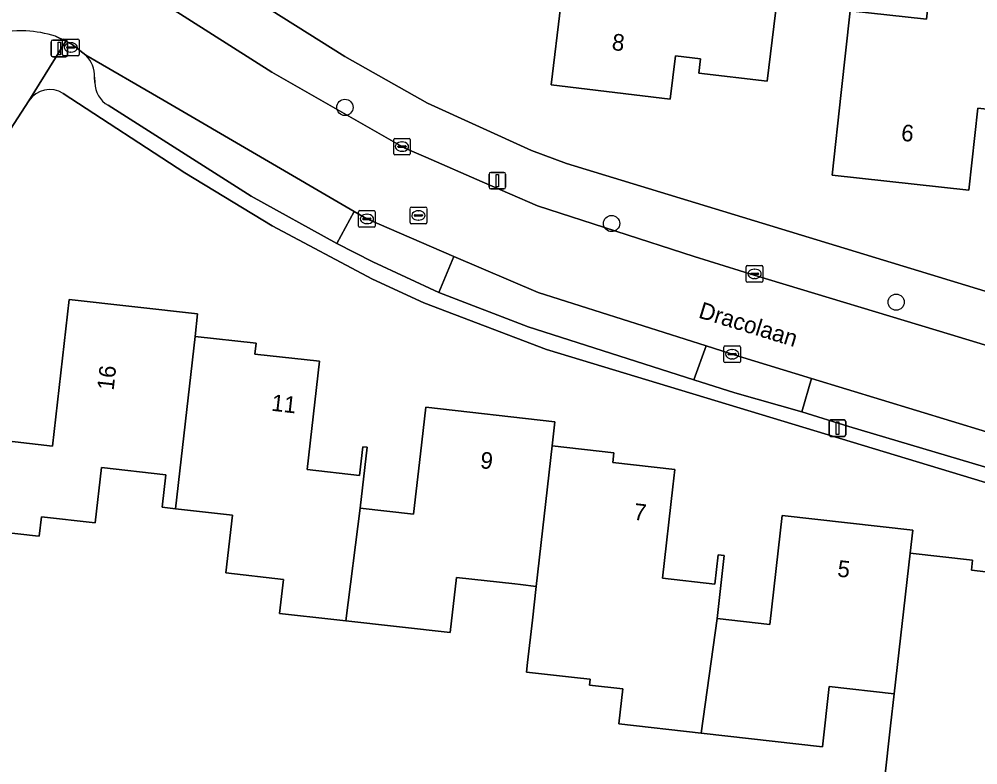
# Model space of a CAD drawing. Extents: x 162396 to 163643, y 386452 to 387406.
# Drawn here: x 162776.3 to 162834, y 386703.6 to 386748.5 of the extents above; entities that cross this region are included whole.
import ezdxf

# ---------------------------------------------------------------- set-up
doc = ezdxf.new("R2010")
doc.units = 0
for name, color, linetype in [('IMGEO_Boom', 7, 'Continuous'), ('IMGEO_Erf', 7, 'Continuous'), ('IMGEO_Kolk', 7, 'Continuous'), ('IMGEO_Lichtmast', 7, 'Continuous'), ('IMGEO_Openbare_ruimte_label', 7, 'Continuous'), ('IMGEO_Pand', 7, 'Continuous'), ('IMGEO_Pand_nummerreeks', 7, 'Continuous'), ('IMGEO_Parkeervlak_open', 7, 'Continuous'), ('IMGEO_Rijbaan_lokaal_open', 7, 'Continuous'), ('IMGEO_Rioolput', 7, 'Continuous'), ('IMGEO_Voetpad_open', 7, 'Continuous')]:
    doc.layers.add(name, color=color, linetype=linetype)

msp = doc.modelspace()

# ---------------------------------------------------------------- linework, layer by layer
at = {"layer": 'IMGEO_Boom'}
for centre in [(162795.943, 386743.185), (162811.991, 386736.195), (162829.12, 386731.463)]:
    msp.add_circle(centre, 0.489, dxfattribs=at)
at = {"layer": 'IMGEO_Erf'}
for points in [[(162821.361, 386744.761), (162817.252, 386745.249), (162817.354, 386746.114), (162815.837, 386746.294), (162815.528, 386743.687), (162808.365, 386744.537), (162808.938, 386749.367), (162810.208, 386749.217), (162810.301, 386750), (162810.679, 386753.193), (162814.991, 386752.681), (162815.198, 386754.42), (162822.406, 386753.564), (162821.983, 386750), (162821.951, 386749.727)], [(162838.302, 386750.511), (162838.246, 386750), (162837.996, 386747.728), (162837.45, 386742.757), (162834.043, 386743.131), (162833.501, 386738.198), (162825.263, 386739.102), (162825.809, 386744.073), (162826.351, 386749.005), (162830.938, 386748.501), (162831.102, 386750), (162831.243, 386751.286), (162831.558, 386754.158), (162838.618, 386753.383)]]:
    msp.add_lwpolyline(points, close=True, dxfattribs=at)
for points in [[(162784.935, 386753.194), (162789.995, 386750), (162795.943, 386746.246), (162800.923, 386743.431), (162807.171, 386740.595), (162809.276, 386739.81), (162887.231, 386716.025)], [(162879.195, 386707.065), (162808.069, 386728.604), (162800.69, 386731.432), (162797.61, 386732.851), (162791.569, 386736.058), (162786.318, 386739.251), (162778.985, 386744.019)], [(162776.93, 386743.582), (162768.744, 386730.951), (162762.934, 386721.672), (162757.742, 386711.279), (162754.454, 386701.785), (162744.409, 386671.894), (162782.247, 386667.715), (162783.774, 386663.035), (162787.296, 386663.004), (162855.09, 386662.415)], [(162772.963, 386723.411), (162778.345, 386722.803), (162779.342, 386731.632), (162787.082, 386730.758), (162786.929, 386729.402), (162790.603, 386728.987), (162790.531, 386728.342), (162794.407, 386727.904), (162793.671, 386721.384), (162796.818, 386721.029), (162797.014, 386722.763), (162797.275, 386722.734), (162796.86, 386719.058), (162800.076, 386718.694), (162800.487, 386722.334), (162800.805, 386725.144), (162808.582, 386724.266), (162808.418, 386722.814), (162812.126, 386722.395), (162812.06, 386721.812), (162815.793, 386721.39), (162815.676, 386720.357), (162815.054, 386714.85), (162818.204, 386714.494), (162818.402, 386716.251), (162818.772, 386716.209), (162818.344, 386712.421), (162821.52, 386712.063), (162822.261, 386718.623), (162830.115, 386717.736), (162829.959, 386716.349), (162833.716, 386715.925), (162833.648, 386715.325), (162837.431, 386714.898)], [(162828.414, 386702.69), (162828.787, 386705.967), (162829.003, 386707.886), (162825.088, 386708.328), (162824.678, 386704.697), (162817.389, 386705.52), (162812.438, 386706.079), (162812.676, 386708.181), (162810.666, 386708.408), (162810.706, 386708.763), (162810.123, 386708.829), (162806.875, 386709.197), (162806.94, 386709.77), (162807.229, 386712.318), (162807.46, 386714.357), (162806.521, 386714.463), (162806.173, 386714.502), (162802.655, 386714.9), (162802.279, 386711.571), (162795.993, 386712.28), (162795.279, 386712.361), (162792.011, 386712.729), (162792.242, 386714.78), (162788.784, 386715.171), (162789.176, 386718.646), (162785.758, 386719.032), (162784.943, 386719.124), (162785.164, 386721.078), (162781.289, 386721.516), (162780.911, 386718.176), (162777.685, 386718.541), (162777.553, 386717.373), (162777.316, 386717.4), (162772.347, 386717.961)]]:
    msp.add_lwpolyline(points, dxfattribs=at)
msp.add_arc((162778.176, 386742.773), 1.486, 57.01486, 146.99561, dxfattribs=at)
at = {"layer": 'IMGEO_Kolk'}
for p, q in [((162778.947, 386746.37), (162778.947, 386747.222)), ((162779.022, 386747.296), (162779.874, 386747.296)), ((162779.435, 386747.076), (162779.46, 386747.076)), ((162779.948, 386747.222), (162779.948, 386746.37)), ((162779.206, 386746.79), (162779.206, 386746.802)), ((162779.644, 386746.753), (162779.246, 386746.753)), ((162779.249, 386746.839), (162779.647, 386746.839)), ((162779.458, 386746.516), (162779.433, 386746.516)), ((162779.69, 386746.802), (162779.69, 386746.79)), ((162779.874, 386746.296), (162779.022, 386746.296)), ((162798.953, 386741.323), (162799.805, 386741.323)), ((162798.878, 386740.397), (162798.878, 386741.249)), ((162799.137, 386740.817), (162799.137, 386740.829)), ((162799.575, 386740.78), (162799.177, 386740.78)), ((162799.18, 386740.866), (162799.578, 386740.866)), ((162799.366, 386741.103), (162799.391, 386741.103)), ((162799.621, 386740.829), (162799.621, 386740.817)), ((162799.879, 386741.249), (162799.879, 386740.397)), ((162799.805, 386740.323), (162798.953, 386740.323)), ((162799.389, 386740.543), (162799.364, 386740.543)), ((162796.768, 386736.044), (162796.768, 386736.896)), ((162796.843, 386736.97), (162797.695, 386736.97)), ((162797.256, 386736.75), (162797.281, 386736.75)), ((162797.769, 386736.896), (162797.769, 386736.044)), ((162797.027, 386736.464), (162797.027, 386736.476)), ((162797.465, 386736.427), (162797.067, 386736.427)), ((162797.07, 386736.513), (162797.468, 386736.513)), ((162797.279, 386736.19), (162797.254, 386736.19)), ((162797.511, 386736.476), (162797.511, 386736.464)), ((162797.695, 386735.97), (162796.843, 386735.97)), ((162820.097, 386732.736), (162820.097, 386733.588)), ((162820.172, 386733.662), (162821.024, 386733.662)), ((162820.585, 386733.442), (162820.61, 386733.442)), ((162821.098, 386733.588), (162821.098, 386732.736)), ((162821.024, 386732.662), (162820.172, 386732.662)), ((162820.356, 386733.156), (162820.356, 386733.168)), ((162820.794, 386733.119), (162820.396, 386733.119)), ((162820.399, 386733.205), (162820.797, 386733.205)), ((162820.608, 386732.882), (162820.583, 386732.882)), ((162820.84, 386733.168), (162820.84, 386733.156)), ((162818.751, 386727.9), (162818.751, 386728.752)), ((162818.826, 386728.826), (162819.678, 386728.826)), ((162819.752, 386728.752), (162819.752, 386727.9)), ((162819.01, 386728.32), (162819.01, 386728.332)), ((162819.448, 386728.283), (162819.05, 386728.283)), ((162819.053, 386728.369), (162819.451, 386728.369)), ((162819.262, 386728.046), (162819.237, 386728.046)), ((162819.239, 386728.606), (162819.264, 386728.606)), ((162819.494, 386728.332), (162819.494, 386728.32)), ((162819.678, 386727.826), (162818.826, 386727.826))]:
    msp.add_line(p, q, dxfattribs=at)
for points in [[(162778.947, 386746.37), (162778.947, 386747.222)], [(162779.022, 386747.296), (162779.874, 386747.296)], [(162779.948, 386747.222), (162779.948, 386746.37)], [(162779.874, 386746.296), (162779.022, 386746.296)], [(162798.953, 386741.323), (162799.805, 386741.323)], [(162798.878, 386740.397), (162798.878, 386741.249)], [(162799.879, 386741.249), (162799.879, 386740.397)], [(162799.805, 386740.323), (162798.953, 386740.323)], [(162796.768, 386736.044), (162796.768, 386736.896)], [(162796.843, 386736.97), (162797.695, 386736.97)], [(162797.769, 386736.896), (162797.769, 386736.044)], [(162797.695, 386735.97), (162796.843, 386735.97)], [(162820.097, 386732.736), (162820.097, 386733.588)], [(162820.172, 386733.662), (162821.024, 386733.662)], [(162821.098, 386733.588), (162821.098, 386732.736)], [(162821.024, 386732.662), (162820.172, 386732.662)], [(162818.751, 386727.9), (162818.751, 386728.752)], [(162818.826, 386728.826), (162819.678, 386728.826)], [(162819.752, 386728.752), (162819.752, 386727.9)], [(162819.678, 386727.826), (162818.826, 386727.826)]]:
    msp.add_lwpolyline(points, dxfattribs=at)
for centre, radius, start, end in [((162779.024, 386747.22), 0.0765, 91.55205, 178.44795), ((162779.024, 386747.22), 0.0765, 91.55205, 178.44795), ((162779.872, 386747.22), 0.0765, 1.55205, 88.44795), ((162779.872, 386747.22), 0.0765, 1.55205, 88.44795), ((162779.246, 386746.799), 0.0403, 85.87752, 175.75265), ((162779.243, 386746.789), 0.0366, 178.93798, 274.71019), ((162779.647, 386746.796), 0.043, 264.86636, 352.45326), ((162779.651, 386746.801), 0.0386, 1.73085, 96.63898), ((162779.024, 386746.372), 0.0765, 181.55205, 268.44795), ((162779.024, 386746.372), 0.0765, 181.55205, 268.44795), ((162779.872, 386746.372), 0.0765, 271.55205, 358.44795), ((162779.872, 386746.372), 0.0765, 271.55205, 358.44795), ((162798.955, 386741.247), 0.0765, 91.55205, 178.44795), ((162798.955, 386741.247), 0.0765, 91.55205, 178.44795), ((162799.803, 386741.247), 0.0765, 1.55205, 88.44795), ((162799.803, 386741.247), 0.0765, 1.55205, 88.44795), ((162799.177, 386740.826), 0.0403, 85.87752, 175.75265), ((162799.174, 386740.816), 0.0366, 178.93798, 274.71019), ((162799.578, 386740.823), 0.043, 264.86636, 352.45326), ((162799.582, 386740.828), 0.0386, 1.73085, 96.63898), ((162798.955, 386740.399), 0.0765, 181.55205, 268.44795), ((162798.955, 386740.399), 0.0765, 181.55205, 268.44795), ((162799.803, 386740.399), 0.0765, 271.55205, 358.44795), ((162799.803, 386740.399), 0.0765, 271.55205, 358.44795), ((162796.845, 386736.894), 0.0765, 91.55205, 178.44795), ((162796.845, 386736.894), 0.0765, 91.55205, 178.44795), ((162797.693, 386736.894), 0.0765, 1.55205, 88.44795), ((162797.693, 386736.894), 0.0765, 1.55205, 88.44795), ((162797.067, 386736.473), 0.0403, 85.87752, 175.75265), ((162797.064, 386736.463), 0.0366, 178.93798, 274.71019), ((162797.468, 386736.47), 0.043, 264.86636, 352.45326), ((162797.472, 386736.475), 0.0386, 1.73085, 96.63898), ((162796.845, 386736.046), 0.0765, 181.55205, 268.44795), ((162796.845, 386736.046), 0.0765, 181.55205, 268.44795), ((162797.693, 386736.046), 0.0765, 271.55205, 358.44795), ((162797.693, 386736.046), 0.0765, 271.55205, 358.44795), ((162820.174, 386733.586), 0.0765, 91.55205, 178.44795), ((162820.174, 386733.586), 0.0765, 91.55205, 178.44795), ((162821.022, 386733.586), 0.0765, 1.55205, 88.44795), ((162821.022, 386733.586), 0.0765, 1.55205, 88.44795), ((162820.174, 386732.738), 0.0765, 181.55205, 268.44795), ((162820.174, 386732.738), 0.0765, 181.55205, 268.44795), ((162820.396, 386733.165), 0.0403, 85.87752, 175.75265), ((162820.393, 386733.155), 0.0366, 178.93798, 274.71019), ((162820.797, 386733.162), 0.043, 264.86636, 352.45326), ((162820.801, 386733.167), 0.0386, 1.73085, 96.63898), ((162821.022, 386732.738), 0.0765, 271.55205, 358.44795), ((162821.022, 386732.738), 0.0765, 271.55205, 358.44795), ((162818.828, 386728.75), 0.0765, 91.55205, 178.44795), ((162818.828, 386728.75), 0.0765, 91.55205, 178.44795), ((162819.676, 386728.75), 0.0765, 1.55205, 88.44795), ((162819.676, 386728.75), 0.0765, 1.55205, 88.44795), ((162819.05, 386728.329), 0.0403, 85.87752, 175.75265), ((162819.047, 386728.319), 0.0366, 178.93798, 274.71019), ((162819.451, 386728.326), 0.043, 264.86636, 352.45326), ((162819.455, 386728.331), 0.0386, 1.73085, 96.63898), ((162818.828, 386727.902), 0.0765, 181.55205, 268.44795), ((162818.828, 386727.902), 0.0765, 181.55205, 268.44795), ((162819.676, 386727.902), 0.0765, 271.55205, 358.44795), ((162819.676, 386727.902), 0.0765, 271.55205, 358.44795)]:
    msp.add_arc(centre, radius, start, end, dxfattribs=at)
for centre, major_axis, ratio, start_param, end_param in [((162779.434, 386746.796), (-0.387, 0.002), 0.722429, 4.712389, 7.853982), ((162779.459, 386746.796), (-0.39, 0.002), 0.717154, 1.570796, 4.712389), ((162799.365, 386740.823), (-0.387, 0.002), 0.722429, 4.712389, 7.853982), ((162799.39, 386740.823), (-0.39, 0.002), 0.717154, 1.570796, 4.712389), ((162797.255, 386736.47), (-0.387, 0.002), 0.722429, 4.712389, 7.853982), ((162797.28, 386736.47), (-0.39, 0.002), 0.717154, 1.570796, 4.712389), ((162820.584, 386733.162), (-0.387, 0.002), 0.722429, 4.712389, 7.853982), ((162820.609, 386733.162), (-0.39, 0.002), 0.717154, 1.570796, 4.712389), ((162819.238, 386728.326), (-0.387, 0.002), 0.722429, 4.712389, 7.853982), ((162819.263, 386728.326), (-0.39, 0.002), 0.717154, 1.570796, 4.712389)]:
    msp.add_ellipse(centre, major_axis=major_axis, ratio=ratio, start_param=start_param, end_param=end_param, dxfattribs=at)
at = {"layer": 'IMGEO_Lichtmast'}
for p, q in [((162778.266, 386746.331), (162778.266, 386747.131)), ((162778.266, 386747.131), (162778.266, 386746.331)), ((162778.366, 386747.231), (162779.156, 386747.231)), ((162779.156, 386747.231), (162778.366, 386747.231)), ((162779.256, 386747.131), (162779.256, 386746.331)), ((162779.256, 386746.331), (162779.256, 386747.131)), ((162779.156, 386746.231), (162778.366, 386746.231)), ((162778.366, 386746.231), (162779.156, 386746.231)), ((162804.625, 386738.374), (162804.625, 386739.174)), ((162804.625, 386739.174), (162804.625, 386738.374)), ((162804.725, 386739.274), (162805.515, 386739.274)), ((162805.515, 386739.274), (162804.725, 386739.274)), ((162805.615, 386739.174), (162805.615, 386738.374)), ((162805.615, 386738.374), (162805.615, 386739.174)), ((162805.515, 386738.274), (162804.725, 386738.274)), ((162804.725, 386738.274), (162805.515, 386738.274)), ((162825.093, 386723.479), (162825.093, 386724.279)), ((162825.093, 386724.279), (162825.093, 386723.479)), ((162825.193, 386724.379), (162825.983, 386724.379)), ((162825.983, 386724.379), (162825.193, 386724.379)), ((162826.083, 386724.279), (162826.083, 386723.479)), ((162826.083, 386723.479), (162826.083, 386724.279)), ((162825.983, 386723.379), (162825.193, 386723.379)), ((162825.193, 386723.379), (162825.983, 386723.379))]:
    msp.add_line(p, q, dxfattribs=at)
for points in [[(162778.686, 386747.106), (162778.836, 386747.106), (162778.836, 386746.356), (162778.686, 386746.356), (162778.686, 386747.106)], [(162805.045, 386739.149), (162805.195, 386739.149), (162805.195, 386738.399), (162805.045, 386738.399), (162805.045, 386739.149)], [(162825.513, 386724.254), (162825.663, 386724.254), (162825.663, 386723.504), (162825.513, 386723.504), (162825.513, 386724.254)]]:
    msp.add_lwpolyline(points, dxfattribs=at)
for centre, start, end in [((162778.366, 386747.131), 90, 180), ((162778.366, 386747.131), 90, 180), ((162779.156, 386747.131), 0, 90), ((162779.156, 386747.131), 360, 90), ((162778.366, 386746.331), 180, 270), ((162778.366, 386746.331), 180, 270), ((162779.156, 386746.331), 270, 0), ((162779.156, 386746.331), 270, 0), ((162804.725, 386739.174), 90, 180), ((162804.725, 386739.174), 90, 180), ((162805.515, 386739.174), 0, 90), ((162805.515, 386739.174), 360, 90), ((162804.725, 386738.374), 180, 270), ((162804.725, 386738.374), 180, 270), ((162805.515, 386738.374), 270, 0), ((162805.515, 386738.374), 270, 0), ((162825.193, 386724.279), 90, 180), ((162825.193, 386724.279), 90, 180), ((162825.983, 386724.279), 0, 90), ((162825.983, 386724.279), 360, 90), ((162825.193, 386723.479), 180, 270), ((162825.193, 386723.479), 180, 270), ((162825.983, 386723.479), 270, 0), ((162825.983, 386723.479), 270, 0)]:
    msp.add_arc(centre, 0.1, start, end, dxfattribs=at)
at = {"layer": 'IMGEO_Pand'}
for points in [[(162808.938, 386749.367), (162808.365, 386744.537), (162815.528, 386743.687), (162815.837, 386746.294), (162817.354, 386746.114), (162817.252, 386745.249), (162821.361, 386744.761), (162821.951, 386749.727), (162821.983, 386750), (162822.406, 386753.564), (162815.198, 386754.42), (162814.991, 386752.681), (162810.679, 386753.193), (162810.301, 386750), (162810.208, 386749.217)], [(162825.263, 386739.102), (162833.501, 386738.198), (162834.043, 386743.131), (162837.45, 386742.757), (162837.996, 386747.728), (162838.246, 386750), (162838.302, 386750.511), (162838.618, 386753.383), (162831.558, 386754.158), (162831.243, 386751.286), (162831.102, 386750), (162830.938, 386748.501), (162826.351, 386749.005), (162825.809, 386744.073)], [(162786.929, 386729.402), (162787.082, 386730.758), (162779.342, 386731.632), (162778.345, 386722.803), (162772.963, 386723.411), (162772.347, 386717.961), (162777.316, 386717.4), (162777.553, 386717.373), (162777.685, 386718.541), (162780.911, 386718.176), (162781.289, 386721.516), (162785.164, 386721.078), (162784.943, 386719.124), (162785.758, 386719.032)], [(162793.671, 386721.384), (162794.407, 386727.904), (162790.531, 386728.342), (162790.603, 386728.987), (162786.929, 386729.402), (162785.758, 386719.032), (162789.176, 386718.646), (162788.784, 386715.171), (162792.242, 386714.78), (162792.011, 386712.729), (162795.279, 386712.361), (162795.993, 386712.28), (162796.86, 386719.058), (162797.275, 386722.734), (162797.014, 386722.763), (162796.818, 386721.029)], [(162808.418, 386722.814), (162808.582, 386724.266), (162800.805, 386725.144), (162800.487, 386722.334), (162800.076, 386718.694), (162796.86, 386719.058), (162795.993, 386712.28), (162802.279, 386711.571), (162802.655, 386714.9), (162806.173, 386714.502), (162806.521, 386714.463), (162807.46, 386714.357)], [(162818.772, 386716.209), (162818.402, 386716.251), (162818.204, 386714.494), (162815.054, 386714.85), (162815.676, 386720.357), (162815.793, 386721.39), (162812.06, 386721.812), (162812.126, 386722.395), (162808.418, 386722.814), (162807.46, 386714.357), (162807.229, 386712.318), (162806.94, 386709.77), (162806.875, 386709.197), (162810.123, 386708.829), (162810.706, 386708.763), (162810.666, 386708.408), (162812.676, 386708.181), (162812.438, 386706.079), (162817.389, 386705.52), (162818.344, 386712.421)], [(162829.959, 386716.349), (162830.115, 386717.736), (162822.261, 386718.623), (162821.52, 386712.063), (162818.344, 386712.421), (162817.389, 386705.52), (162824.678, 386704.697), (162825.088, 386708.328), (162829.003, 386707.886)], [(162837.327, 386713.973), (162837.431, 386714.898), (162833.648, 386715.325), (162833.716, 386715.925), (162829.959, 386716.349), (162829.003, 386707.886), (162828.787, 386705.967), (162828.414, 386702.69), (162832.588, 386702.219), (162839.521, 386701.436), (162840.097, 386706.535), (162840.386, 386709.774), (162840.079, 386709.809), (162839.876, 386708.014), (162836.694, 386708.373)]]:
    msp.add_lwpolyline(points, close=True, dxfattribs=at)
at = {"layer": 'IMGEO_Parkeervlak_open'}
for points in [[(162784.993, 386743.639), (162780.358, 386746.319)], [(162780.869, 386745.008), (162780.893, 386744.679)], [(162781.691, 386743.311), (162790.297, 386737.833), (162795.456, 386734.999), (162796.507, 386736.913), (162784.993, 386743.639)]]:
    msp.add_lwpolyline(points, dxfattribs=at)
for points in [[(162807.574, 386732.04), (162802.505, 386734.22), (162801.587, 386732.054), (162806.98, 386729.981), (162816.952, 386726.782), (162817.68, 386728.827)], [(162824.019, 386726.87), (162823.437, 386724.861), (162826.267, 386723.977), (162838.14, 386720.442), (162838.761, 386722.377)]]:
    msp.add_lwpolyline(points, close=True, dxfattribs=at)
for centre, radius, start, end in [((162779.133, 386745.086), 1.738, 357.41253, 45.17704), ((162782.499, 386744.699), 1.606, 180.72325, 239.78963)]:
    msp.add_arc(centre, radius, start, end, dxfattribs=at)
at = {"layer": 'IMGEO_Rijbaan_lokaal_open'}
for points in [[(162885.432, 386713.389), (162867.077, 386719.017), (162863.426, 386720.121), (162851.256, 386723.803), (162847.632, 386724.899), (162836.03, 386728.409), (162832.38, 386729.513), (162820.57, 386733.086), (162816.968, 386734.216), (162807.535, 386737.268), (162804.196, 386738.713), (162800.806, 386740.18), (162799.553, 386740.722), (162791.551, 386745.306), (162784.174, 386750), (162782.452, 386751.096), (162782.216, 386751.254), (162781.987, 386751.424)], [(162778.517, 386747.471), (162779.146, 386747.164), (162779.528, 386746.978), (162780.358, 386746.319), (162784.993, 386743.639), (162796.507, 386736.913), (162797.254, 386736.477), (162802.505, 386734.22), (162807.574, 386732.04), (162817.68, 386728.827), (162819.637, 386728.205), (162824.019, 386726.87), (162838.761, 386722.377), (162845.069, 386720.455), (162879.001, 386710.115), (162880.077, 386709.787)]]:
    msp.add_lwpolyline(points, dxfattribs=at)
for points in [[(162797.254, 386736.477), (162796.507, 386736.913), (162795.456, 386734.999), (162797.619, 386733.887), (162801.587, 386732.054), (162802.505, 386734.22)], [(162824.019, 386726.87), (162819.637, 386728.205), (162817.68, 386728.827), (162816.952, 386726.782), (162819.417, 386726.01), (162823.437, 386724.861)]]:
    msp.add_lwpolyline(points, close=True, dxfattribs=at)
for centre, radius, start, end in [((162776.481, 386741.309), 6.484, 87.6552, 126.80427), ((162776.391, 386740.697), 7.1, 72.57266, 87.13097)]:
    msp.add_arc(centre, radius, start, end, dxfattribs=at)
at = {"layer": 'IMGEO_Rioolput'}
for p, q in [((162799.868, 386736.258), (162799.868, 386737.11)), ((162799.943, 386737.184), (162800.795, 386737.184)), ((162800.127, 386736.678), (162800.127, 386736.69)), ((162800.17, 386736.727), (162800.568, 386736.727)), ((162800.356, 386736.964), (162800.381, 386736.964)), ((162800.611, 386736.69), (162800.611, 386736.678)), ((162800.869, 386737.11), (162800.869, 386736.258)), ((162800.795, 386736.184), (162799.943, 386736.184)), ((162800.565, 386736.641), (162800.167, 386736.641)), ((162800.379, 386736.404), (162800.354, 386736.404))]:
    msp.add_line(p, q, dxfattribs=at)
for points in [[(162799.868, 386736.258), (162799.868, 386737.11)], [(162799.943, 386737.184), (162800.795, 386737.184)], [(162800.869, 386737.11), (162800.869, 386736.258)], [(162800.795, 386736.184), (162799.943, 386736.184)]]:
    msp.add_lwpolyline(points, dxfattribs=at)
for centre, radius, start, end in [((162799.945, 386737.108), 0.0765, 91.55205, 178.44795), ((162799.945, 386737.108), 0.0765, 91.55205, 178.44795), ((162800.167, 386736.687), 0.0403, 85.87752, 175.75265), ((162800.572, 386736.689), 0.0386, 1.73085, 96.63898), ((162800.793, 386737.108), 0.0765, 1.55205, 88.44795), ((162800.793, 386737.108), 0.0765, 1.55205, 88.44795), ((162799.945, 386736.26), 0.0765, 181.55205, 268.44795), ((162799.945, 386736.26), 0.0765, 181.55205, 268.44795), ((162800.164, 386736.677), 0.0366, 178.93798, 274.71019), ((162800.568, 386736.684), 0.043, 264.86636, 352.45326), ((162800.793, 386736.26), 0.0765, 271.55205, 358.44795), ((162800.793, 386736.26), 0.0765, 271.55205, 358.44795)]:
    msp.add_arc(centre, radius, start, end, dxfattribs=at)
for centre, major_axis, ratio, start_param, end_param in [((162800.355, 386736.684), (-0.387, 0.002), 0.722429, 4.712389, 7.853982), ((162800.38, 386736.684), (-0.39, 0.002), 0.717154, 1.570796, 4.712389)]:
    msp.add_ellipse(centre, major_axis=major_axis, ratio=ratio, start_param=start_param, end_param=end_param, dxfattribs=at)
at = {"layer": 'IMGEO_Voetpad_open'}
for points in [[(162784.464, 386755.3), (162784.401, 386755.228), (162781.987, 386751.424), (162782.216, 386751.254), (162782.452, 386751.096), (162784.174, 386750), (162791.551, 386745.306), (162799.553, 386740.722), (162800.806, 386740.18), (162804.196, 386738.713), (162807.535, 386737.268), (162816.968, 386734.216), (162820.57, 386733.086), (162832.38, 386729.513), (162836.03, 386728.409), (162847.632, 386724.899), (162851.256, 386723.803), (162863.426, 386720.121), (162867.077, 386719.017), (162885.432, 386713.389)], [(162809.276, 386739.81), (162807.171, 386740.595), (162800.923, 386743.431), (162795.943, 386746.246), (162789.995, 386750), (162784.935, 386753.194)], [(162754.454, 386701.785), (162757.742, 386711.279), (162762.934, 386721.672), (162768.744, 386730.951), (162776.93, 386743.582), (162779.146, 386747.164), (162778.517, 386747.471)], [(162780.358, 386746.319), (162779.528, 386746.978), (162779.146, 386747.164), (162776.93, 386743.582)], [(162780.893, 386744.679), (162780.869, 386745.008)], [(162778.985, 386744.019), (162786.318, 386739.251), (162791.569, 386736.058), (162797.61, 386732.851), (162800.69, 386731.432), (162808.069, 386728.604), (162879.195, 386707.065)], [(162844.481, 386718.603), (162842.897, 386719.077), (162838.14, 386720.442), (162826.267, 386723.977), (162823.437, 386724.861), (162819.417, 386726.01), (162816.952, 386726.782), (162806.98, 386729.981), (162801.587, 386732.054), (162797.619, 386733.887), (162795.456, 386734.999), (162790.297, 386737.833), (162781.691, 386743.311)], [(162887.231, 386716.025), (162809.276, 386739.81)]]:
    msp.add_lwpolyline(points, dxfattribs=at)
for centre, radius, start, end in [((162776.481, 386741.309), 6.484, 87.6552, 126.80427), ((162776.391, 386740.697), 7.1, 72.57266, 87.13097), ((162779.133, 386745.086), 1.738, 357.41253, 45.17704), ((162778.176, 386742.773), 1.486, 57.01486, 146.99561), ((162782.499, 386744.699), 1.606, 180.72325, 239.78963)]:
    msp.add_arc(centre, radius, start, end, dxfattribs=at)

# ---------------------------------------------------------------- texts
at = {"layer": 'IMGEO_Openbare_ruimte_label'}
msp.add_text('Dracolaan', height=1, rotation=342.96046, dxfattribs=at).set_placement((162817.167, 386730.544))
at = {"layer": 'IMGEO_Pand_nummerreeks'}
for s, rotation, p in [('8', 353.23262, (162811.974, 386746.647)), ('6', 353.73768, (162829.383, 386741.185)), ('16', 83.55726, (162782.02, 386726.119)), ('11', 353.55422, (162791.483, 386724.933)), ('9', 353.55995, (162804.052, 386721.477)), ('7', 353.5485, (162813.285, 386718.373)), ('5', 353.55654, (162825.546, 386714.951))]:
    msp.add_text(s, height=1, rotation=rotation, dxfattribs=at).set_placement(p)

doc.saveas('drawing.dxf')
